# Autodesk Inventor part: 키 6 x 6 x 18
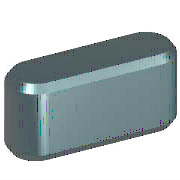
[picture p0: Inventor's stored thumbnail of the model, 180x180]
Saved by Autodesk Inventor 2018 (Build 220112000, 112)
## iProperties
IsCustomPart: 1
Created: 2012-02
Part Number: 키 6 x 6 x 18
Material: 강철, 연강
Description: 키 및 해당 키홈
Document SubType Name: Modeling
Standard: KS B 1311
Designer: mduedu
Standards Organization: KS
Language: ko-KR
Size Designation: 6 x 6 x 18
Categories: <MemberInstance><Categories><Category DisplayName="샤프트 부품" InternalName="7f7aeb1f-a693-4053-b835-cee3144e0d98" Mnemonic="SHFT"><Category DisplayName="키" Interna
Density: 1 g/cm^3
Appearance: 노란색
Author: mduedu
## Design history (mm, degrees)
workplane "Work Plane1"
workplane "Work Plane2"
sketch "스케치1"
  geometry: L1 (3, 3)-(15, 3); L2 (15, -3)-(3, -3); L3 (0, 9.4)-(0, -7.4) reference; L4 (-5, 0)-(30, 0) reference; L5 (18, 0)-(18, 7); A1 r 3 centre (3, 0) between (3, 3) and (3, -3); A2 r 3 centre (15, 0) between (15, -3) and (15, 3)
  constraints: 6 end point, 5 point on circle, 4 tangent, 3 point on line, 2 centre point, 1 horizontal, 1 parallel, 1 perpendicular
  dimensions: "d0" = 3 radius of A1 (= 0.5 x PB); "d13" = 3 radius of A2 (= 0.5 x PB); "d14" = 18 distance between parallel lines of L5 L3 (= NLG)
extrude "본체1" new body sketch "스케치1" taper "d3" = 0 deg; stored distance "d4" = 10
workplane "Work Plane3"
body "Solid1"
chamfer "모따기1" distance "d8" = 0.4 (= PHH); stored, may be unused: second distance "d9" = 0.4 (= PHH), angle "d15" = 45 deg
other parameters: "d1" = -3.5 (= -PNT), "d2" = 2.5 (= PH - PNT), "NLG" = 18 [user parameter; used in 3 equation terms], "PB" = 6 [user parameter; used in 2 equation terms], "PNT" = 3.5 [user parameter; used in 2 equation terms], "PH" = 6 [user parameter; used in 1 equation term], "PHH" = 0.4 [user parameter; used in 2 equation terms], "d10" = 0, "d16" = 0, "d17" = 0, "d18" = 0, "WDMIN" = 17 [user parameter], "PLB2" = 18 (= NLG) [user parameter], "WDMAX" = 22 [user parameter], "PLB1" = 18 (= NLG) [user parameter], "RR" = 0.16 [user parameter], "PUEB" = 2.8 [user parameter]
